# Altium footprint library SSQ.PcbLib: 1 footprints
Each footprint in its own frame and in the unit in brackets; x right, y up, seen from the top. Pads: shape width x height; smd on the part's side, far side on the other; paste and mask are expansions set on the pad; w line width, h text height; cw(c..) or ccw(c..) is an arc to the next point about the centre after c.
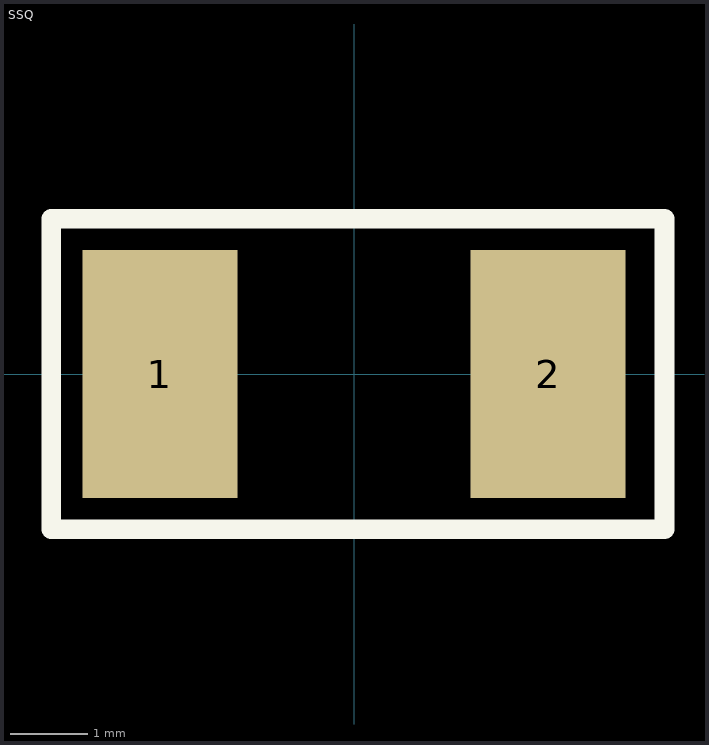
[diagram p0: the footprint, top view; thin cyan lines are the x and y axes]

## SSQ [mm] "BEL FUSE INC SSQ FUSE"
height 2.54
pads (2):
  rect 2x3.2 smd: 1(-2.5,0) 2(2.5,0)
Top Overlay:
  lines w0.254: -3.9,-2 -3.9,2 4,2 4,-2 -3.9,-2
M5 Assembly Top:
  text ".Designator" at 0,-0.1 h1.02
3D body: height 2.54, standoff 0, extent -3.9,-2 4,2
